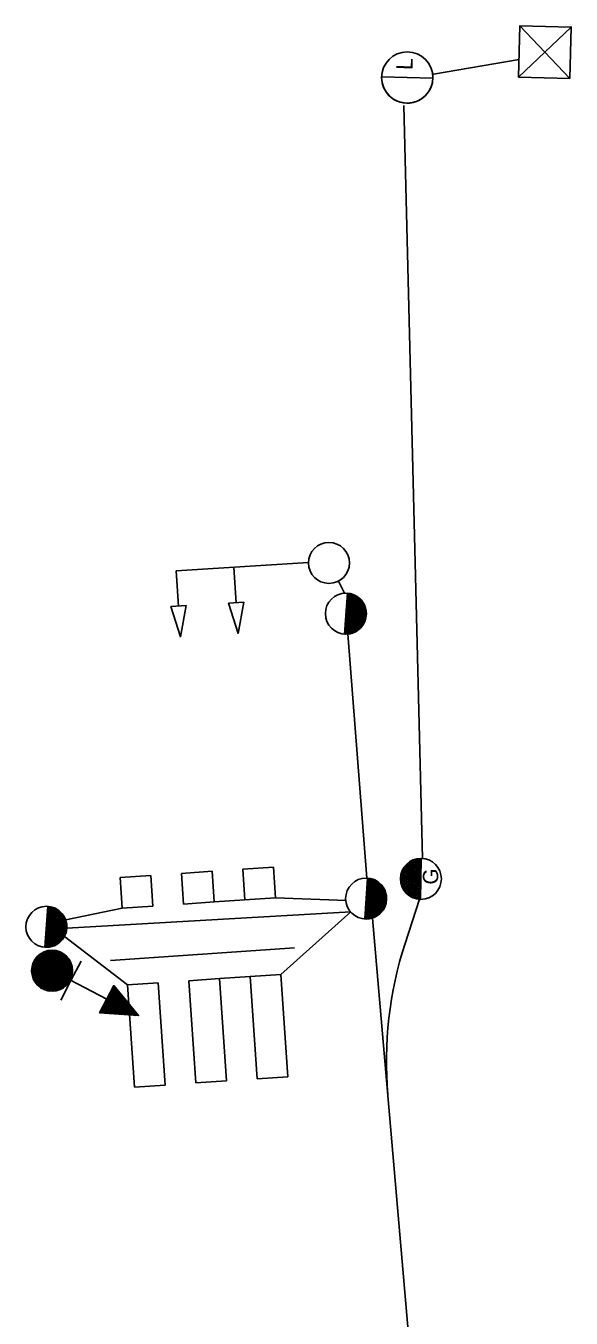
# Model space of a CAD drawing. Extents: x 584850 to 602551, y 145475 to 158627.
# Drawn here: x 585857.1 to 585963.5, y 153137.7 to 153389.9 of the extents above; entities that cross this region are included whole.
import ezdxf

# ---------------------------------------------------------------- set-up
doc = ezdxf.new("R2010")
doc.units = 0
doc.layers.add('Default', color=7, linetype='Continuous')
doc.layers.add('P_LTG', color=7, linetype='Continuous')

msp = doc.modelspace()

# ---------------------------------------------------------------- linework, layer by layer
at = {"layer": 'Default'}
for p, q in [((585934.47, 153227.41), (585930.83, 153374.34)), ((585912.25, 153285.17), (585886.47, 153283.51)), ((585898.14, 153277.3), (585897.7, 153284.17)), ((585886.91, 153276.64), (585886.47, 153283.51)), ((585919.29, 153279.17), (585918.11, 153281.53)), ((585919.84, 153279.17), (585919.26, 153271.19)), ((585919.74, 153277.89), (585920.94, 153278.92)), ((585919.77, 153278.23), (585920.67, 153279.01)), ((585919.79, 153278.56), (585920.39, 153279.08)), ((585919.82, 153278.9), (585920.09, 153279.14)), ((585923.51, 153274.64), (585919.82, 153278.9)), ((585919.84, 153279.17), (585919.84, 153279.17)), ((585919.84, 153279.17), (585919.84, 153279.17)), ((585923.53, 153274.98), (585919.91, 153279.16)), ((585923.54, 153275.33), (585920.28, 153279.1)), ((585923.49, 153275.76), (585920.68, 153279)), ((585919.4, 153273.15), (585923.3, 153276.52)), ((585919.43, 153273.49), (585923.22, 153276.76)), ((585919.45, 153273.82), (585923.1, 153276.98)), ((585919.47, 153274.16), (585922.99, 153277.2)), ((585919.5, 153274.5), (585922.86, 153277.41)), ((585919.52, 153274.84), (585922.71, 153277.6)), ((585919.55, 153275.18), (585922.57, 153277.79)), ((585919.57, 153275.52), (585922.4, 153277.97)), ((585919.6, 153275.86), (585922.23, 153278.13)), ((585919.62, 153276.19), (585922.05, 153278.3)), ((585919.65, 153276.53), (585921.85, 153278.44)), ((585922.81, 153272.87), (585919.65, 153276.53)), ((585919.67, 153276.87), (585921.64, 153278.57)), ((585922.94, 153273.09), (585919.67, 153276.87)), ((585919.7, 153277.21), (585921.43, 153278.71)), ((585923.07, 153273.31), (585919.7, 153277.21)), ((585919.72, 153277.55), (585921.18, 153278.81)), ((585923.19, 153273.54), (585919.72, 153277.55)), ((585923.29, 153273.79), (585919.74, 153277.89)), ((585923.38, 153274.05), (585919.77, 153278.23)), ((585923.45, 153274.34), (585919.79, 153278.56)), ((585923.39, 153276.23), (585921.15, 153278.83)), ((585923.16, 153276.87), (585921.75, 153278.5)), ((585919.28, 153271.45), (585923.53, 153275.14)), ((585919.3, 153271.79), (585923.53, 153275.45)), ((585919.33, 153272.13), (585923.49, 153275.74)), ((585919.34, 153271.19), (585923.52, 153274.81)), ((585919.35, 153272.47), (585923.46, 153276.02)), ((585919.38, 153272.81), (585923.38, 153276.27)), ((585921.36, 153271.62), (585919.45, 153273.82)), ((585921.57, 153271.74), (585919.47, 153274.16)), ((585921.78, 153271.86), (585919.5, 153274.5)), ((585921.97, 153272.01), (585919.52, 153274.84)), ((585922.16, 153272.16), (585919.55, 153275.18)), ((585922.34, 153272.32), (585919.57, 153275.52)), ((585922.5, 153272.5), (585919.6, 153275.86)), ((585922.66, 153272.68), (585919.62, 153276.19)), ((585919.71, 153271.19), (585923.47, 153274.44)), ((585920.12, 153271.23), (585923.39, 153274.06)), ((585919.51, 153271.19), (585919.28, 153271.45)), ((585919.82, 153271.2), (585919.3, 153271.79)), ((585920.11, 153271.23), (585919.33, 153272.13)), ((585920.38, 153271.28), (585919.35, 153272.47)), ((585920.65, 153271.34), (585919.38, 153272.81)), ((585920.89, 153271.43), (585919.4, 153273.15)), ((585921.13, 153271.51), (585919.43, 153273.49)), ((585920.59, 153271.32), (585923.2, 153273.58)), ((585921.22, 153271.55), (585922.88, 153272.98)), ((585919.3, 153271.19), (585919.26, 153271.23)), ((585923.61, 153223.58), (585919.91, 153271.2)), ((585934.18, 153227.42), (585930.2, 153223.58)), ((585934.26, 153227.15), (585930.2, 153223.25)), ((585934.25, 153226.82), (585930.22, 153222.93)), ((585933.81, 153227.39), (585930.23, 153223.95)), ((585934.24, 153226.48), (585930.27, 153222.65)), ((585933.4, 153227.33), (585930.29, 153224.34)), ((585934.24, 153226.14), (585930.33, 153222.37)), ((585932.94, 153227.22), (585930.45, 153224.82)), ((585932.32, 153226.96), (585930.74, 153225.44)), ((585931.09, 153225.94), (585934.17, 153222.74)), ((585931.24, 153226.13), (585934.18, 153223.08)), ((585931.42, 153226.29), (585934.19, 153223.42)), ((585931.6, 153226.46), (585934.19, 153223.76)), ((585931.78, 153226.61), (585934.2, 153224.1)), ((585931.98, 153226.74), (585934.21, 153224.44)), ((585932.19, 153226.88), (585934.21, 153224.78)), ((585932.41, 153227), (585934.22, 153225.12)), ((585932.65, 153227.1), (585934.22, 153225.46)), ((585932.88, 153227.2), (585934.23, 153225.8)), ((585933.14, 153227.27), (585934.24, 153226.14)), ((585933.42, 153227.34), (585934.24, 153226.48)), ((585933.7, 153227.38), (585934.25, 153226.82)), ((585934.02, 153227.4), (585934.26, 153227.15)), ((585934.11, 153219.42), (585934.26, 153227.42)), ((585934.22, 153227.42), (585934.26, 153227.38)), ((585881.5, 153224.09), (585875.51, 153223.68)), ((585875.51, 153223.68), (585875.92, 153217.69)), ((585881.9, 153218.1), (585881.5, 153224.09)), ((585893.47, 153224.9), (585887.48, 153224.49)), ((585887.48, 153224.49), (585887.89, 153218.51)), ((585893.88, 153218.92), (585893.47, 153224.9)), ((585905.44, 153225.72), (585899.46, 153225.31)), ((585899.46, 153225.31), (585899.86, 153219.32)), ((585905.85, 153219.73), (585905.44, 153225.72)), ((585923.8, 153223.57), (585923.23, 153215.59)), ((585923.73, 153222.63), (585924.64, 153223.41)), ((585923.76, 153222.97), (585924.35, 153223.48)), ((585923.78, 153223.3), (585924.06, 153223.54)), ((585923.8, 153223.57), (585923.8, 153223.57)), ((585923.8, 153223.57), (585923.8, 153223.57)), ((585927.5, 153219.38), (585923.88, 153223.56)), ((585927.51, 153219.73), (585924.24, 153223.51)), ((585927.46, 153220.16), (585924.65, 153223.41)), ((585930.2, 153223.41), (585934.04, 153219.43)), ((585930.21, 153223.75), (585934.12, 153219.69)), ((585930.25, 153224.05), (585934.12, 153220.03)), ((585930.3, 153224.35), (585934.13, 153220.37)), ((585930.38, 153224.61), (585934.14, 153220.71)), ((585934.23, 153225.8), (585930.42, 153222.12)), ((585930.46, 153224.86), (585934.14, 153221.05)), ((585934.22, 153225.46), (585930.51, 153221.88)), ((585930.57, 153225.1), (585934.15, 153221.39)), ((585934.22, 153225.12), (585930.61, 153221.64)), ((585930.69, 153225.33), (585934.15, 153221.73)), ((585934.21, 153224.78), (585930.73, 153221.43)), ((585930.8, 153225.55), (585934.16, 153222.06)), ((585934.21, 153224.44), (585930.86, 153221.22)), ((585930.95, 153225.75), (585934.17, 153222.4)), ((585934.2, 153224.1), (585931, 153221.02)), ((585934.19, 153223.76), (585931.15, 153220.83)), ((585934.19, 153223.42), (585931.31, 153220.65)), ((585938.1, 153224.41), (585937.99, 153224.36)), ((585923.37, 153217.55), (585927.27, 153220.92)), ((585923.39, 153217.89), (585927.18, 153221.17)), ((585923.42, 153218.23), (585927.07, 153221.38)), ((585923.44, 153218.56), (585926.95, 153221.6)), ((585923.46, 153218.9), (585926.82, 153221.81)), ((585923.49, 153219.24), (585926.68, 153222)), ((585923.51, 153219.58), (585926.53, 153222.19)), ((585923.54, 153219.92), (585926.37, 153222.37)), ((585923.56, 153220.26), (585926.19, 153222.53)), ((585923.59, 153220.6), (585926.02, 153222.7)), ((585923.61, 153220.93), (585925.81, 153222.84)), ((585926.78, 153217.27), (585923.61, 153220.93)), ((585923.64, 153221.27), (585925.6, 153222.98)), ((585926.91, 153217.49), (585923.64, 153221.27)), ((585923.66, 153221.61), (585925.39, 153223.11)), ((585927.04, 153217.71), (585923.66, 153221.61)), ((585923.69, 153221.95), (585925.15, 153223.22)), ((585927.15, 153217.94), (585923.69, 153221.95)), ((585923.71, 153222.29), (585924.9, 153223.32)), ((585927.25, 153218.19), (585923.71, 153222.29)), ((585927.35, 153218.45), (585923.73, 153222.63)), ((585927.41, 153218.74), (585923.76, 153222.97)), ((585927.47, 153219.04), (585923.78, 153223.3)), ((585927.36, 153220.64), (585925.12, 153223.23)), ((585927.12, 153221.28), (585925.72, 153222.9)), ((585930.21, 153223.05), (585933.67, 153219.46)), ((585930.28, 153222.64), (585933.26, 153219.54)), ((585930.4, 153222.16), (585932.78, 153219.69)), ((585930.67, 153221.54), (585932.16, 153219.99)), ((585934.18, 153223.08), (585931.48, 153220.49)), ((585934.17, 153222.74), (585931.67, 153220.33)), ((585934.17, 153222.4), (585931.85, 153220.18)), ((585934.16, 153222.06), (585932.06, 153220.05)), ((585934.15, 153221.73), (585932.28, 153219.92)), ((585934.15, 153221.39), (585932.5, 153219.8)), ((585934.14, 153221.05), (585932.75, 153219.7)), ((585893.88, 153218.92), (585887.89, 153218.51)), ((585893.88, 153218.92), (585899.86, 153219.32)), ((585905.85, 153219.73), (585899.86, 153219.32)), ((585905.85, 153219.73), (585919.68, 153219.2)), ((585923.24, 153215.86), (585927.5, 153219.54)), ((585923.27, 153216.19), (585927.5, 153219.86)), ((585923.29, 153216.53), (585927.46, 153220.14)), ((585923.31, 153215.59), (585927.49, 153219.21)), ((585923.32, 153216.87), (585927.42, 153220.42)), ((585923.34, 153217.21), (585927.35, 153220.68)), ((585925.53, 153216.14), (585923.44, 153218.56)), ((585925.75, 153216.27), (585923.46, 153218.9)), ((585925.94, 153216.41), (585923.49, 153219.24)), ((585926.12, 153216.56), (585923.51, 153219.58)), ((585926.31, 153216.72), (585923.54, 153219.92)), ((585926.47, 153216.9), (585923.56, 153220.26)), ((585926.62, 153217.08), (585923.59, 153220.6)), ((585923.68, 153215.6), (585927.43, 153218.84)), ((585924.09, 153215.63), (585927.35, 153218.46)), ((585933.9, 153219.43), (585931.11, 153210.81)), ((585934.14, 153220.71), (585933, 153219.61)), ((585934.13, 153220.37), (585933.27, 153219.54)), ((585934.12, 153220.03), (585933.56, 153219.48)), ((585934.12, 153219.69), (585933.86, 153219.44)), ((585934.11, 153219.42), (585934.11, 153219.42)), ((585934.11, 153219.42), (585934.11, 153219.42)), ((585861.4, 153218.05), (585860.82, 153210.07)), ((585861.01, 153212.7), (585864.66, 153215.86)), ((585861.03, 153213.04), (585864.55, 153216.08)), ((585861.06, 153213.38), (585864.42, 153216.29)), ((585861.08, 153213.72), (585864.27, 153216.48)), ((585861.11, 153214.06), (585864.13, 153216.67)), ((585861.13, 153214.39), (585863.96, 153216.84)), ((585861.16, 153214.73), (585863.79, 153217.01)), ((585861.18, 153215.07), (585863.61, 153217.17)), ((585861.21, 153215.41), (585863.41, 153217.31)), ((585861.23, 153215.75), (585863.2, 153217.45)), ((585861.25, 153216.09), (585862.99, 153217.58)), ((585864.63, 153212.18), (585861.25, 153216.09)), ((585861.28, 153216.43), (585862.74, 153217.69)), ((585864.75, 153212.42), (585861.28, 153216.43)), ((585861.3, 153216.76), (585862.5, 153217.8)), ((585864.84, 153212.67), (585861.3, 153216.76)), ((585861.33, 153217.1), (585862.23, 153217.88)), ((585864.94, 153212.92), (585861.33, 153217.1)), ((585861.35, 153217.44), (585861.95, 153217.95)), ((585865.01, 153213.22), (585861.35, 153217.44)), ((585861.38, 153217.78), (585861.65, 153218.02)), ((585865.07, 153213.52), (585861.38, 153217.78)), ((585861.4, 153218.05), (585861.4, 153218.04)), ((585861.4, 153218.05), (585861.4, 153218.04)), ((585865.09, 153213.86), (585861.47, 153218.04)), ((585865.1, 153214.21), (585861.84, 153217.98)), ((585865.05, 153214.63), (585862.24, 153217.88)), ((585864.95, 153215.11), (585862.71, 153217.7)), ((585864.72, 153215.75), (585863.31, 153217.38)), ((585875.92, 153217.69), (585864.88, 153215.4)), ((585865.1, 153213.77), (585920.49, 153216.96)), ((585881.9, 153218.1), (585875.92, 153217.69)), ((585906.87, 153204.77), (585920.49, 153216.96)), ((585923.47, 153215.59), (585923.24, 153215.86)), ((585923.79, 153215.6), (585923.27, 153216.19)), ((585924.07, 153215.63), (585923.29, 153216.53)), ((585924.35, 153215.68), (585923.32, 153216.87)), ((585924.62, 153215.74), (585923.34, 153217.21)), ((585924.86, 153215.83), (585923.37, 153217.55)), ((585925.1, 153215.92), (585923.39, 153217.89)), ((585925.32, 153216.02), (585923.42, 153218.23)), ((585924.55, 153215.72), (585927.17, 153217.98)), ((585925.18, 153215.95), (585926.84, 153217.38)), ((585860.84, 153210.33), (585865.09, 153214.01)), ((585860.86, 153210.67), (585865.09, 153214.33)), ((585860.89, 153211.01), (585865.05, 153214.61)), ((585860.9, 153210.07), (585865.08, 153213.69)), ((585860.91, 153211.35), (585865.01, 153214.9)), ((585860.94, 153211.69), (585864.94, 153215.15)), ((585860.96, 153212.02), (585864.86, 153215.4)), ((585860.99, 153212.36), (585864.78, 153215.64)), ((585863.34, 153210.74), (585861.06, 153213.38)), ((585863.53, 153210.89), (585861.08, 153213.72)), ((585863.72, 153211.04), (585861.11, 153214.06)), ((585863.9, 153211.19), (585861.13, 153214.39)), ((585864.06, 153211.38), (585861.16, 153214.73)), ((585864.22, 153211.56), (585861.18, 153215.07)), ((585864.37, 153211.75), (585861.21, 153215.41)), ((585864.5, 153211.97), (585861.23, 153215.75)), ((585861.27, 153210.07), (585865.03, 153213.32)), ((585923.27, 153215.59), (585923.23, 153215.63)), ((585861.67, 153210.11), (585860.89, 153211.01)), ((585861.94, 153210.16), (585860.91, 153211.35)), ((585862.21, 153210.21), (585860.94, 153211.69)), ((585862.45, 153210.3), (585860.96, 153212.02)), ((585862.69, 153210.39), (585860.99, 153212.36)), ((585862.92, 153210.5), (585861.01, 153212.7)), ((585863.13, 153210.62), (585861.03, 153213.04)), ((585861.68, 153210.11), (585864.95, 153212.93)), ((585862.15, 153210.19), (585864.76, 153212.46)), ((585862.78, 153210.42), (585864.44, 153211.86)), ((585876.94, 153202.73), (585864.64, 153212.17)), ((585864.99, 153208.37), (585858.32, 153206.27)), ((585864.77, 153208.56), (585858.37, 153206.53)), ((585864.54, 153208.74), (585858.47, 153206.82)), ((585864.29, 153208.91), (585858.57, 153207.1)), ((585863.99, 153209.06), (585858.73, 153207.4)), ((585863.66, 153209.21), (585858.91, 153207.71)), ((585863.27, 153209.34), (585859.17, 153208.04)), ((585859.34, 153208.25), (585861.45, 153201.58)), ((585862.77, 153209.44), (585859.5, 153208.4)), ((585859.53, 153208.43), (585861.72, 153201.52)), ((585859.73, 153208.6), (585861.97, 153201.51)), ((585859.93, 153208.76), (585862.23, 153201.5)), ((585862.09, 153209.47), (585860.04, 153208.82)), ((585860.15, 153208.89), (585862.48, 153201.5)), ((585860.36, 153209.01), (585862.72, 153201.53)), ((585860.57, 153209.12), (585862.96, 153201.56)), ((585860.8, 153209.21), (585863.2, 153201.62)), ((585860.86, 153210.07), (585860.82, 153210.11)), ((585861.07, 153210.07), (585860.84, 153210.33)), ((585861.38, 153210.07), (585860.86, 153210.67)), ((585861.02, 153209.29), (585863.43, 153201.69)), ((585861.26, 153209.36), (585863.66, 153201.75)), ((585861.49, 153209.41), (585863.88, 153201.86)), ((585861.73, 153209.45), (585864.1, 153201.96)), ((585861.98, 153209.47), (585864.31, 153202.08)), ((585862.22, 153209.47), (585864.52, 153202.23)), ((585862.48, 153209.48), (585864.72, 153202.37)), ((585862.74, 153209.44), (585864.92, 153202.54)), ((585863, 153209.4), (585865.11, 153202.74)), ((585863.28, 153209.34), (585865.3, 153202.93)), ((585863.56, 153209.25), (585865.47, 153203.18)), ((585863.84, 153209.14), (585865.65, 153203.43)), ((585864.14, 153208.98), (585865.8, 153203.73)), ((585864.45, 153208.8), (585865.95, 153204.05)), ((585864.78, 153208.55), (585866.08, 153204.46)), ((585873.6, 153207.51), (585909.52, 153209.96)), ((585865.35, 153207.98), (585858.24, 153205.74)), ((585865.49, 153207.78), (585858.24, 153205.49)), ((585865.63, 153207.57), (585858.24, 153205.23)), ((585865.17, 153208.18), (585858.27, 153206)), ((585865.76, 153207.36), (585858.27, 153204.99)), ((585858.28, 153206.04), (585859.32, 153202.74)), ((585865.85, 153207.14), (585858.31, 153204.75)), ((585865.95, 153206.92), (585858.35, 153204.51)), ((585858.37, 153206.54), (585859.67, 153202.42)), ((585866.03, 153206.69), (585858.43, 153204.29)), ((585858.5, 153206.91), (585860, 153202.18)), ((585866.09, 153206.46), (585858.5, 153204.06)), ((585866.15, 153206.22), (585858.59, 153203.83)), ((585858.65, 153207.26), (585860.32, 153201.98)), ((585866.19, 153205.98), (585858.71, 153203.62)), ((585858.81, 153207.54), (585860.61, 153201.84)), ((585866.2, 153205.74), (585858.82, 153203.4)), ((585858.98, 153207.81), (585860.9, 153201.72)), ((585859.16, 153208.03), (585861.18, 153201.64)), ((585865.14, 153208.2), (585866.18, 153204.93)), ((585865.57, 153207.66), (585866.21, 153205.62)), ((585865.89, 153203.58), (585867.87, 153207.39)), ((585858.24, 153205.36), (585858.9, 153203.27)), ((585866.22, 153205.49), (585858.96, 153203.2)), ((585866.21, 153205.24), (585859.12, 153202.99)), ((585866.18, 153204.98), (585859.28, 153202.79)), ((585866.15, 153204.71), (585859.47, 153202.6)), ((585866.07, 153204.44), (585859.68, 153202.42)), ((585866, 153204.16), (585859.91, 153202.24)), ((585865.87, 153203.87), (585860.17, 153202.07)), ((585865.73, 153203.58), (585860.46, 153201.91)), ((585865.53, 153203.26), (585860.8, 153201.76)), ((585865.89, 153203.58), (585863.92, 153199.77)), ((585865.81, 153203.63), (585872.88, 153199.96)), ((585894.9, 153203.95), (585888.91, 153203.54)), ((585890.27, 153183.59), (585888.91, 153203.54)), ((585894.9, 153203.95), (585900.88, 153204.36)), ((585896.25, 153184), (585894.9, 153203.95)), ((585906.87, 153204.77), (585900.88, 153204.36)), ((585902.24, 153184.4), (585900.88, 153204.36)), ((585908.23, 153184.81), (585906.87, 153204.77)), ((585865.31, 153202.94), (585861.19, 153201.64)), ((585864.95, 153202.57), (585861.65, 153201.53)), ((585864.42, 153202.15), (585862.32, 153201.49)), ((585875.84, 153200.68), (585872.75, 153199.7)), ((585875.67, 153200.89), (585872.91, 153200.02)), ((585875.5, 153201.1), (585873.07, 153200.33)), ((585875.33, 153201.31), (585873.23, 153200.65)), ((585873.33, 153200.83), (585874.52, 153197.07)), ((585875.16, 153201.52), (585873.4, 153200.96)), ((585873.49, 153201.15), (585874.79, 153197.05)), ((585874.99, 153201.73), (585873.56, 153201.27)), ((585873.66, 153201.46), (585875.06, 153197.03)), ((585874.82, 153201.93), (585873.72, 153201.59)), ((585873.82, 153201.77), (585875.33, 153197.01)), ((585874.65, 153202.14), (585873.89, 153201.9)), ((585873.98, 153202.09), (585875.6, 153196.99)), ((585874.48, 153202.35), (585874.05, 153202.21)), ((585874.15, 153202.4), (585875.86, 153196.97)), ((585874.31, 153202.56), (585874.21, 153202.53)), ((585874.39, 153202.45), (585876.13, 153196.95)), ((585874.82, 153201.93), (585876.4, 153196.93)), ((585875.25, 153201.41), (585876.67, 153196.91)), ((585875.67, 153200.89), (585876.94, 153196.89)), ((585882.92, 153203.14), (585876.94, 153202.73)), ((585878.29, 153182.77), (585876.94, 153202.73)), ((585884.28, 153183.18), (585882.92, 153203.14)), ((585877.04, 153199.23), (585871.6, 153197.51)), ((585877.21, 153199.02), (585871.7, 153197.28)), ((585876.87, 153199.43), (585871.77, 153197.82)), ((585876.7, 153199.64), (585871.93, 153198.14)), ((585872.03, 153198.32), (585872.37, 153197.23)), ((585876.53, 153199.85), (585872.09, 153198.45)), ((585872.19, 153198.64), (585872.64, 153197.21)), ((585876.36, 153200.06), (585872.26, 153198.76)), ((585872.35, 153198.95), (585872.91, 153197.19)), ((585877.38, 153198.81), (585872.37, 153197.23)), ((585876.18, 153200.27), (585872.42, 153199.08)), ((585872.52, 153199.26), (585873.18, 153197.17)), ((585876.01, 153200.48), (585872.58, 153199.39)), ((585872.68, 153199.58), (585873.45, 153197.15)), ((585872.84, 153199.89), (585873.72, 153197.13)), ((585873.01, 153200.21), (585873.99, 153197.11)), ((585877.55, 153198.6), (585873.05, 153197.18)), ((585873.17, 153200.52), (585874.25, 153197.09)), ((585877.72, 153198.39), (585873.72, 153197.13)), ((585877.89, 153198.19), (585874.39, 153197.08)), ((585876.1, 153200.37), (585877.21, 153196.87)), ((585876.53, 153199.85), (585877.48, 153196.85)), ((585876.95, 153199.33), (585877.74, 153196.83)), ((585877.38, 153198.81), (585878.01, 153196.81)), ((585877.81, 153198.29), (585878.28, 153196.79)), ((585871.54, 153197.38), (585871.57, 153197.29)), ((585871.7, 153197.7), (585871.84, 153197.27)), ((585871.86, 153198.01), (585872.11, 153197.25)), ((585878.06, 153197.98), (585875.06, 153197.03)), ((585878.23, 153197.77), (585875.73, 153196.98)), ((585878.4, 153197.56), (585876.4, 153196.93)), ((585878.57, 153197.35), (585877.07, 153196.88)), ((585878.75, 153197.14), (585877.74, 153196.83)), ((585878.23, 153197.77), (585878.55, 153196.77)), ((585878.92, 153196.94), (585878.42, 153196.78)), ((585878.66, 153197.25), (585878.82, 153196.75)), ((585879.09, 153196.73), (585879.09, 153196.73)), ((585884.28, 153183.18), (585878.29, 153182.77)), ((585896.25, 153184), (585890.27, 153183.59)), ((585908.23, 153184.81), (585902.24, 153184.4))]:
    msp.add_line(p, q, dxfattribs=at)
for points in [[(585888.41, 153276.74), (585887.3, 153270.65), (585885.41, 153276.55)], [(585899.64, 153277.4), (585898.53, 153271.31), (585896.65, 153277.21)], [(585874.26, 153202.62), (585879.09, 153196.73), (585871.49, 153197.29)]]:
    msp.add_lwpolyline(points, close=True, dxfattribs=at)
msp.add_lwpolyline([(585924.77, 153215.78), (585947.39, 152953.8)], dxfattribs=at)
for centre in [(585916.25, 153285.07), (585919.55, 153275.18), (585934.19, 153223.42), (585923.51, 153219.58), (585861.11, 153214.06), (585862.23, 153205.49)]:
    msp.add_circle(centre, 4, dxfattribs=at)
for centre, radius, start, end in [((585919.55, 153275.18), 4, 265.8628, 85.8628), ((585934.19, 153223.42), 4, 88.9257, 268.9257), ((585923.51, 153219.58), 4, 265.8628, 85.8628), ((585861.11, 153214.06), 4, 265.8628, 85.8628), ((586002.47, 153187.74), 75, 162.0863, 184.9348)]:
    msp.add_arc(centre, radius, start, end, dxfattribs=at)
at = {"layer": 'P_LTG'}
for p, q in [((585963.25, 153379.62), (585953.51, 153389.87)), ((585953.26, 153379.87), (585963.51, 153389.62)), ((585953.34, 153383.28), (585936.65, 153380.42)), ((585936.53, 153379.65), (585926.53, 153379.91))]:
    msp.add_line(p, q, dxfattribs=at)
msp.add_lwpolyline([(585963.25, 153379.62), (585963.51, 153389.62), (585953.51, 153389.87), (585953.26, 153379.87)], close=True, dxfattribs=at)
msp.add_circle((585931.53, 153379.78), 5, dxfattribs=at)
msp.add_arc((585931.53, 153379.78), 5, 178.5538, 358.5538, dxfattribs=at)

# ---------------------------------------------------------------- texts
at = {"layer": 'Default'}
msp.add_text('G', height=3, rotation=89.3623, dxfattribs=at).set_placement((585937.56, 153222.29))
at = {"layer": 'P_LTG'}
msp.add_text('L', height=3.15, rotation=88.5538, dxfattribs=at).set_placement((585932.54, 153381.22))

doc.saveas('drawing.dxf')
